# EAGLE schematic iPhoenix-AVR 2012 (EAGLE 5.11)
COMPANY: AL-AWAIL; DATE-YEAR: 11

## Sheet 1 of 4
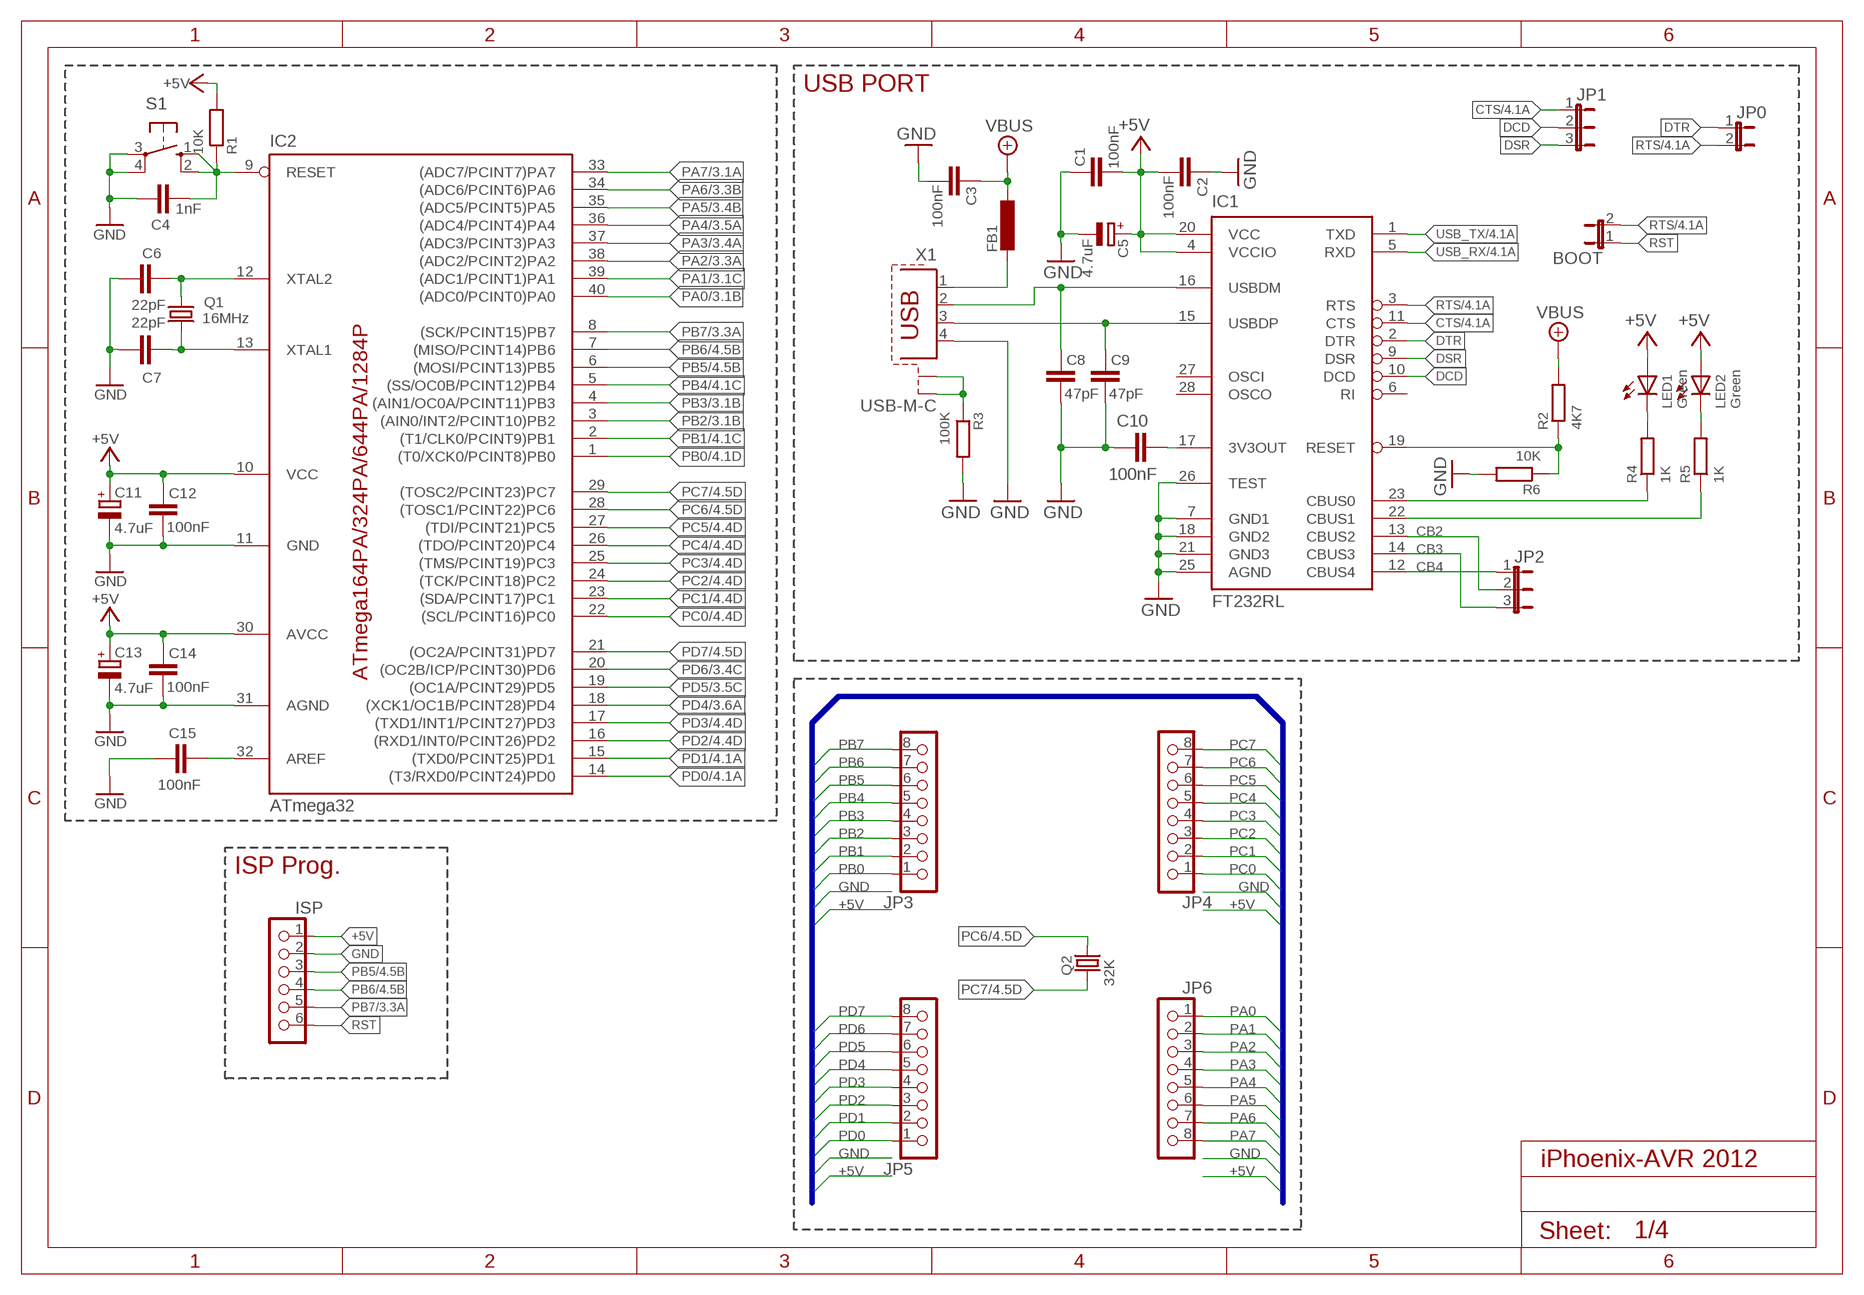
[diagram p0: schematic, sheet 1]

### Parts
BOOT  JP1E  [JP1]
C1  100nF  CAPC025-025X050  [C025-025X050]
C2  100nF  CAPC025-025X050  [C025-025X050]
C3  100nF  CAPC025-025X050  [C025-025X050]
C4  1nF  CAPC025-025X050  [C025-025X050]
C5  4.7uF  ELCE2,5-5  [E2,5-5]
C6  22pF  CAPC025-025X050  [C025-025X050]
C7  22pF  CAPC025-025X050  [C025-025X050]
C8  47pF  CAPC025-025X050  [C025-025X050]
C9  47pF  CAPC025-025X050  [C025-025X050]
C10  100nF  CAPC025-025X050  [C025-025X050]
C11  4.7uF  ELCE2,5-5  [E2,5-5]
C12  100nF  CAPC025-025X050  [C025-025X050]
C13  4.7uF  ELCE2,5-5  [E2,5-5]
C14  100nF  CAPC025-025X050  [C025-025X050]
C15  100nF  CAPC025-025X050  [C025-025X050]
FB1  FB1206  [R1206]
IC1  FT232RL  [SSOP28]
IC2  ATmega32  ATMEGA324P  [DIL40]
ISP  PINHD-1X6  [1X06]
JP0  JP1E  [JP1]
JP1  JP2EA  [JP2]
JP2  JP2EA  [JP2]
JP3  PINHD-1X8  [1X08]
JP4  PINHD-1X8  [1X08]
JP5  PINHD-1X8  [1X08]
JP6  PINHD-1X8  [1X08]
LED1  Green  LED3  [LED3MM]
LED2  Green  LED3  [LED3MM]
Q1  16MHz  CRYSTALHC  [HC49]
Q2  32K  CRYSTALTC  [TC26]
R1  10K  RESISTOR0207/8  [0207/8]
R2  4K7  RESISTOR0207/8  [0207/8]
R3  100K  RESISTOR0207/8  [0207/8]
R4  1K  RESISTOR0207/8  [0207/8]
R5  1K  RESISTOR0207/8  [0207/8]
R6  10K  RESISTOR0207/8  [0207/8]
S1  TAC_SW_M  [B3F-10XX]
X1  USB-M-C  [PN61729-S]

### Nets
+5V: C1.2 C2.2 C5.+ C11.+ C12.1 C13.+ C14.1 IC1.4(VCCIO) IC1.20(VCC) IC2.10(VCC) IC2.30(AVCC) ISP.1 LED1.A LED2.A R1.2 ; also sheet 2,3,4
+5V/1: C3.1 FB1.1 R2.2 ; supply symbol labelled VBUS ; also sheet 2
CB2: IC1.13(CBUS2) JP2.2
CB3: IC1.14(CBUS3) JP2.3
CB4: IC1.12(CBUS4) JP2.1
CTS: IC1.11(CTS) JP1.1 ; also sheet 4
DCD: IC1.10(DCD) JP1.2
DSR: IC1.9(DSR) JP1.3
DTR: IC1.2(DTR) JP0.1
GND: C1.1 C2.1 C3.2 C4.1 C5.- C6.2 C7.2 C8.2 C9.2 C10.2 C11.- C12.2 C13.- C14.2 C15.2 IC1.7(GND1) IC1.18(GND2) IC1.21(GND3) IC1.25(AGND) IC1.26(TEST) IC2.11(GND) IC2.31(AGND) ISP.2 R3.2 R6.2 S1.3(P) S1.4(P1) X1.4 ; also sheet 2,3,4
N$2: C6.1 IC2.12(XTAL2) Q1.1
N$8: C15.1 IC2.32(AREF)
N$13: R3.1 X1.S1 X1.S2
N$161: IC1.23(CBUS0) R4.1
N$197: C8.1 IC1.16(USBDM) X1.2
N$199: C9.1 IC1.15(USBDP) X1.3
N$200: C10.1 IC1.17(3V3OUT)
N$201: IC1.19(RESET) R2.1 R6.1
N$202: IC1.22(CBUS1) R5.1
N$203: LED1.K(C) R4.2
N$235: LED2.K(C) R5.2
PA0: IC2.40((ADC0/PCINT0)PA0) JP6.1 ; also sheet 3
PA1: IC2.39((ADC1/PCINT1)PA1) JP6.2 ; also sheet 3
PA2: IC2.38((ADC2/PCINT2)PA2) JP6.3 ; also sheet 3
PA3: IC2.37((ADC3/PCINT3)PA3) JP6.4 ; also sheet 3
PA4: IC2.36((ADC4/PCINT4)PA4) JP6.5 ; also sheet 3
PA5: IC2.35((ADC5/PCINT5)PA5) JP6.6 ; also sheet 3
PA6: IC2.34((ADC6/PCINT6)PA6) JP6.7 ; also sheet 3
PA7: IC2.33((ADC7/PCINT7)PA7) JP6.8 ; also sheet 3
PB0: IC2.1((T0/XCK0/PCINT8)PB0) JP3.1 ; also sheet 2,4
PB1: IC2.2((T1/CLK0/PCINT9)PB1) JP3.2 ; also sheet 2,4
PB2: IC2.3((AIN0/INT2/PCINT10)PB2) JP3.3 ; also sheet 2,3,4
PB3: IC2.4((AIN1/OC0A/PCINT11)PB3) JP3.4 ; also sheet 2,3,4
PB4: IC2.5((SS/OC0B/PCINT12)PB4) JP3.5 ; also sheet 2,4
PB5: IC2.6((MOSI/PCINT13)PB5) ISP.3 JP3.6 ; also sheet 2,4
PB6: IC2.7((MISO/PCINT14)PB6) ISP.4 JP3.7 ; also sheet 2,4
PB7: IC2.8((SCK/PCINT15)PB7) ISP.5 JP3.8 ; also sheet 2,3,4
PC0: IC2.22((SCL/PCINT16)PC0) JP4.1 ; also sheet 2,4
PC1: IC2.23((SDA/PCINT17)PC1) JP4.2 ; also sheet 2,4
PC2: IC2.24((TCK/PCINT18)PC2) JP4.3 ; also sheet 2,4
PC3: IC2.25((TMS/PCINT19)PC3) JP4.4 ; also sheet 2,4
PC4: IC2.26((TDO/PCINT20)PC4) JP4.5 ; also sheet 2,4
PC5: IC2.27((TDI/PCINT21)PC5) JP4.6 ; also sheet 2,4
PC6: IC2.28((TOSC1/PCINT22)PC6) JP4.7 Q2.2 ; also sheet 2,4
PC7: IC2.29((TOSC2/PCINT23)PC7) JP4.8 Q2.1 ; also sheet 2,4
PD0: IC2.14((T3/RXD0/PCINT24)PD0) JP5.1 ; also sheet 4
PD1: IC2.15((TXD0/PCINT25)PD1) JP5.2 ; also sheet 4
PD2: IC2.16((RXD1/INT0/PCINT26)PD2) JP5.3 ; also sheet 2,4
PD3: IC2.17((TXD1/INT1/PCINT27)PD3) JP5.4 ; also sheet 2,4
PD4: IC2.18((XCK1/OC1B/PCINT28)PD4) JP5.5 ; also sheet 3,4
PD5: IC2.19((OC1A/PCINT29)PD5) JP5.6 ; also sheet 3,4
PD6: IC2.20((OC2B/ICP/PCINT30)PD6) JP5.7 ; also sheet 3,4
PD7: IC2.21((OC2A/PCINT31)PD7) JP5.8 ; also sheet 4
RST: BOOT.1 C4.2 IC2.9(RESET) ISP.6 R1.1 S1.1(S) S1.2(S1)
RTS: BOOT.2 IC1.3(RTS) JP0.2 ; also sheet 4
USB_RX: IC1.5(RXD) ; also sheet 4
USB_TX: IC1.1(TXD) ; also sheet 4
VUSB: FB1.2 X1.1
XT2: C7.1 IC2.13(XTAL1) Q1.2
Unconnected: IC1.6(RI) IC1.27(OSCI) IC1.28(OSCO)

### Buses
PA[0..7],PB[0..7],PC[0..7],PD[0..7],PE[0..7],PF[0..7],+5V,GND

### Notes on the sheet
- USB PORT
- ISP Prog.

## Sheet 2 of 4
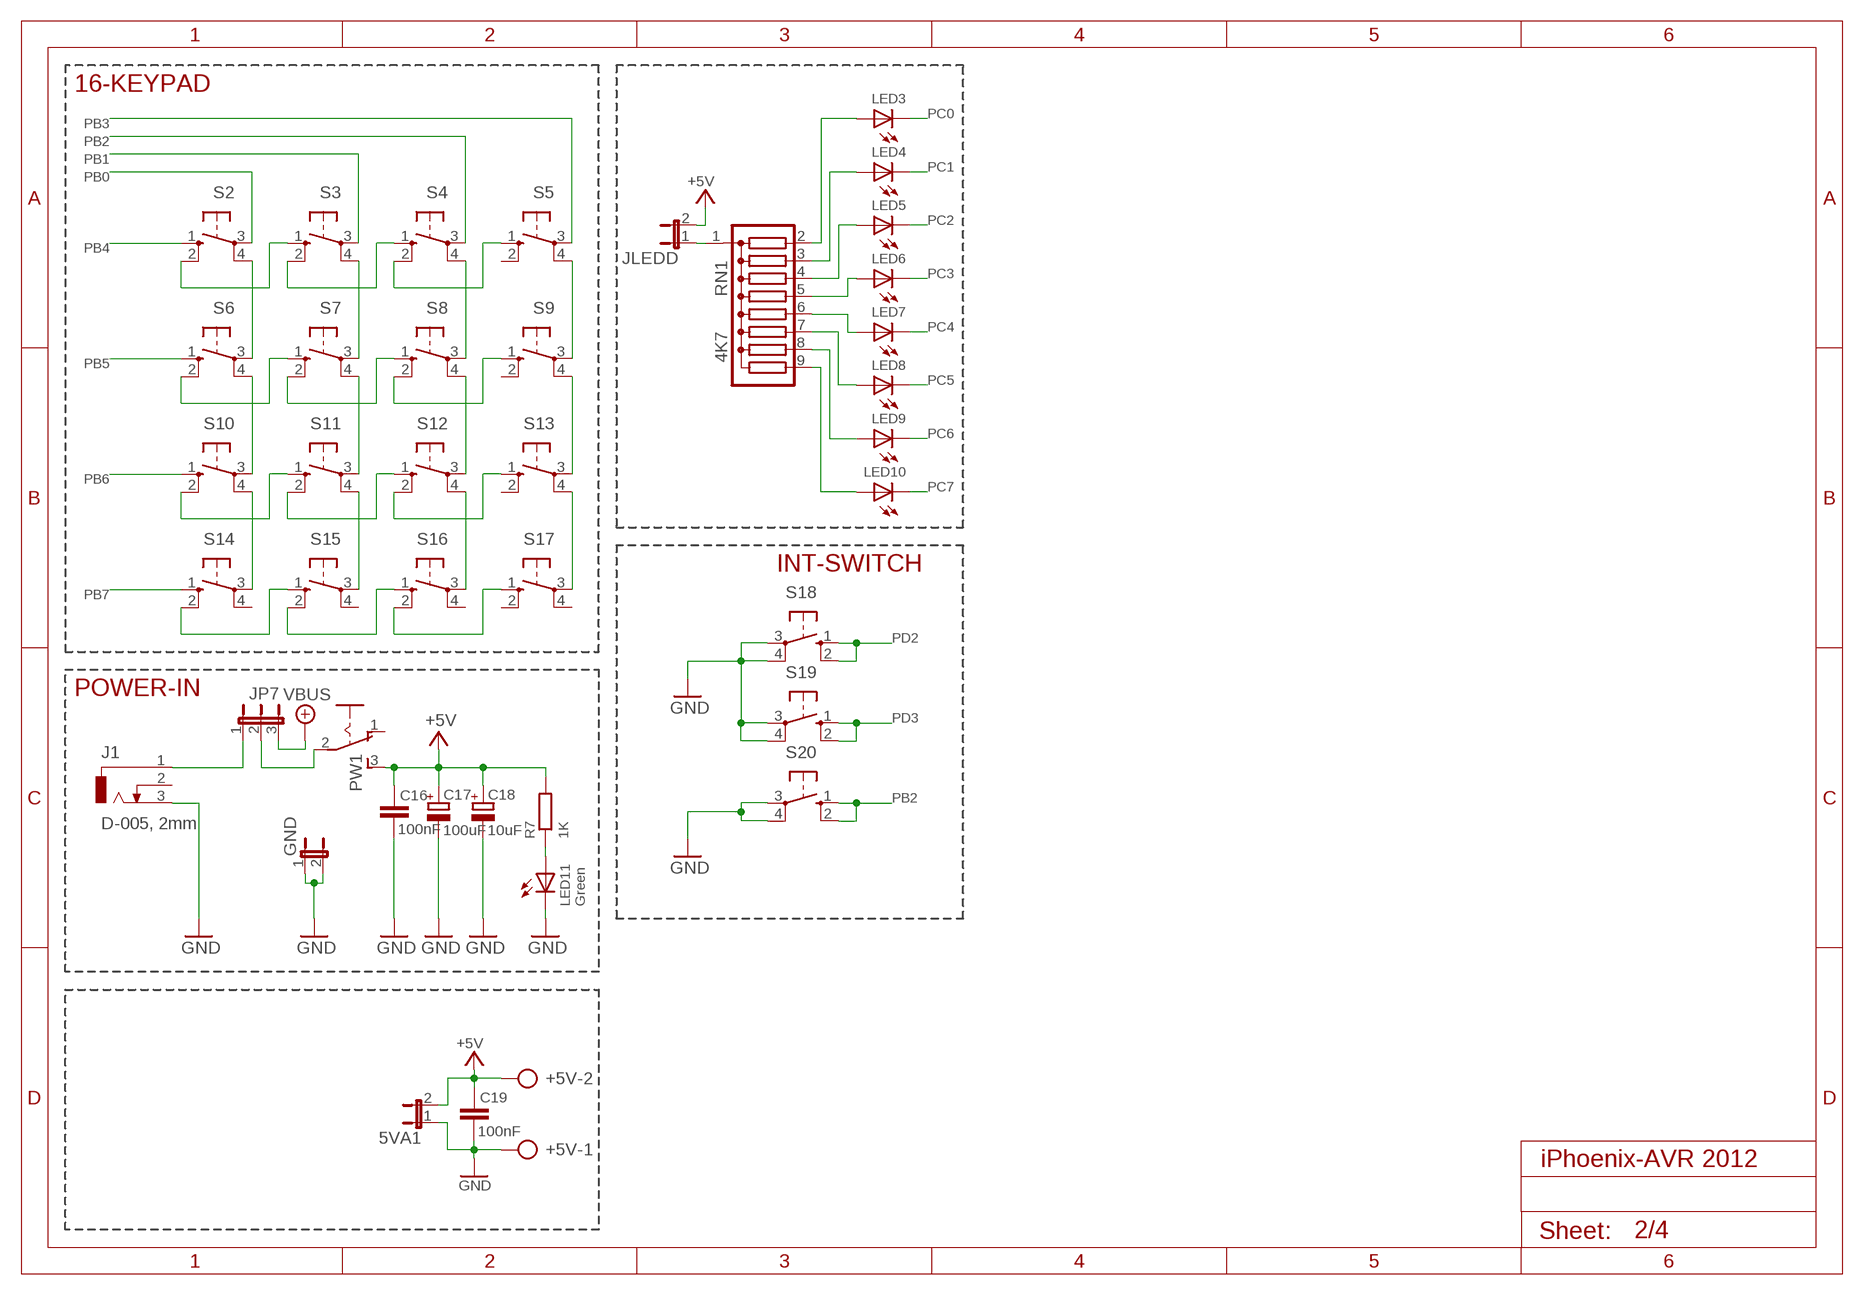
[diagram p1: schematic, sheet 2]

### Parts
5VA1  JP1E  [JP1]
+5V  AK500/2  [AK500/2]
C16  100nF  CAPC025-025X050  [C025-025X050]
C17  100uF  ELCE2,5-5  [E2,5-5]
C18  10uF  ELCE2,5-5  [E2,5-5]
C19  100nF  CAPC025-025X050  [C025-025X050]
GND  JP1E  [JP1]
J1  D-005, 2mm  DCJ0202  [DCJ0202]
JLEDD  JP1E  [JP1]
JP7  JP2EA  [JP2]
LED3  LED3  [LED3MM]
LED4  LED3  [LED3MM]
LED5  LED3  [LED3MM]
LED6  LED3  [LED3MM]
LED7  LED3  [LED3MM]
LED8  LED3  [LED3MM]
LED9  LED3  [LED3MM]
LED10  LED3  [LED3MM]
LED11  Green  LED3  [LED3MM]
PW1  SW-ON-OFF3  [230SB]
R7  1K  RESISTOR0207/8  [0207/8]
RN1  4K7  G08R  [SIL9]
S2  TAC_SW_M  [B3F-10XX]
S3  TAC_SW_M  [B3F-10XX]
S4  TAC_SW_M  [B3F-10XX]
S5  TAC_SW_M  [B3F-10XX]
S6  TAC_SW_M  [B3F-10XX]
S7  TAC_SW_M  [B3F-10XX]
S8  TAC_SW_M  [B3F-10XX]
S9  TAC_SW_M  [B3F-10XX]
S10  TAC_SW_M  [B3F-10XX]
S11  TAC_SW_M  [B3F-10XX]
S12  TAC_SW_M  [B3F-10XX]
S13  TAC_SW_M  [B3F-10XX]
S14  TAC_SW_M  [B3F-10XX]
S15  TAC_SW_M  [B3F-10XX]
S16  TAC_SW_M  [B3F-10XX]
S17  TAC_SW_M  [B3F-10XX]
S18  TAC_SW_M  [B3F-10XX]
S19  TAC_SW_M  [B3F-10XX]
S20  TAC_SW_M  [B3F-10XX]

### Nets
+5V: 5VA1.2 +5V.2 C16.1 C17.+ C18.+ C19.1 JLEDD.2 PW1.3(S) R7.2 ; also sheet 1,3,4
+5V/1: JP7.3 ; supply symbol labelled VBUS ; also sheet 1
GND: 5VA1.1 +5V.1 C16.2 C17.- C18.- C19.2 GND.1 GND.2 J1.3 LED11.K(C) S18.3(P) S18.4(P1) S19.3(P) S19.4(P1) S20.3(P) S20.4(P1) ; also sheet 1,3,4
N$14: LED11.A R7.1
N$15: J1.1 JP7.1
N$16: JP7.2 PW1.2(P)
N$36: S2.2(S1) S3.1(S)
N$37: S3.2(S1) S4.1(S)
N$38: S4.2(S1) S5.1(S)
N$39: S10.2(S1) S11.1(S)
N$40: S11.2(S1) S12.1(S)
N$41: S12.2(S1) S13.1(S)
N$60: S6.2(S1) S7.1(S)
N$61: S7.2(S1) S8.1(S)
N$62: S8.2(S1) S9.1(S)
N$65: S14.2(S1) S15.1(S)
N$66: S15.2(S1) S16.1(S)
N$67: S2.4(P1) S6.3(P)
N$68: S3.4(P1) S7.3(P)
N$69: S4.4(P1) S8.3(P)
N$70: S5.4(P1) S9.3(P)
N$71: S16.2(S1) S17.1(S)
N$73: S10.4(P1) S14.3(P)
N$74: S11.4(P1) S15.3(P)
N$75: S12.4(P1) S16.3(P)
N$76: S13.4(P1) S17.3(P)
N$77: S6.4(P1) S10.3(P)
N$78: S7.4(P1) S11.3(P)
N$79: S8.4(P1) S12.3(P)
N$80: S9.4(P1) S13.3(P)
N$288: JLEDD.1 RN1.1
N$293: LED3.A RN1.2
N$294: LED4.A RN1.3
N$295: LED5.A RN1.4
N$296: LED6.A RN1.5
N$297: LED10.A RN1.9
N$298: LED9.A RN1.8
N$299: LED8.A RN1.7
N$303: LED7.A RN1.6
PB0: S2.3(P) ; also sheet 1,4
PB1: S3.3(P) ; also sheet 1,4
PB2: S4.3(P) S20.1(S) S20.2(S1) ; also sheet 1,3,4
PB3: S5.3(P) ; also sheet 1,3,4
PB4: S2.1(S) ; also sheet 1,4
PB5: S6.1(S) ; also sheet 1,4
PB6: S10.1(S) ; also sheet 1,4
PB7: S14.1(S) ; also sheet 1,3,4
PC0: LED3.K(C) ; also sheet 1,4
PC1: LED4.K(C) ; also sheet 1,4
PC2: LED5.K(C) ; also sheet 1,4
PC3: LED6.K(C) ; also sheet 1,4
PC4: LED7.K(C) ; also sheet 1,4
PC5: LED8.K(C) ; also sheet 1,4
PC6: LED9.K(C) ; also sheet 1,4
PC7: LED10.K(C) ; also sheet 1,4
PD2: S18.1(S) S18.2(S1) ; also sheet 1,4
PD3: S19.1(S) S19.2(S1) ; also sheet 1,4
Unconnected: J1.2 PW1.1(O) S5.2(S1) S9.2(S1) S13.2(S1) S14.4(P1) S15.4(P1) S16.4(P1) S17.2(S1) S17.4(P1)

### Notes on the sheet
- 16-KEYPAD
- INT-SWITCH
- POWER-IN

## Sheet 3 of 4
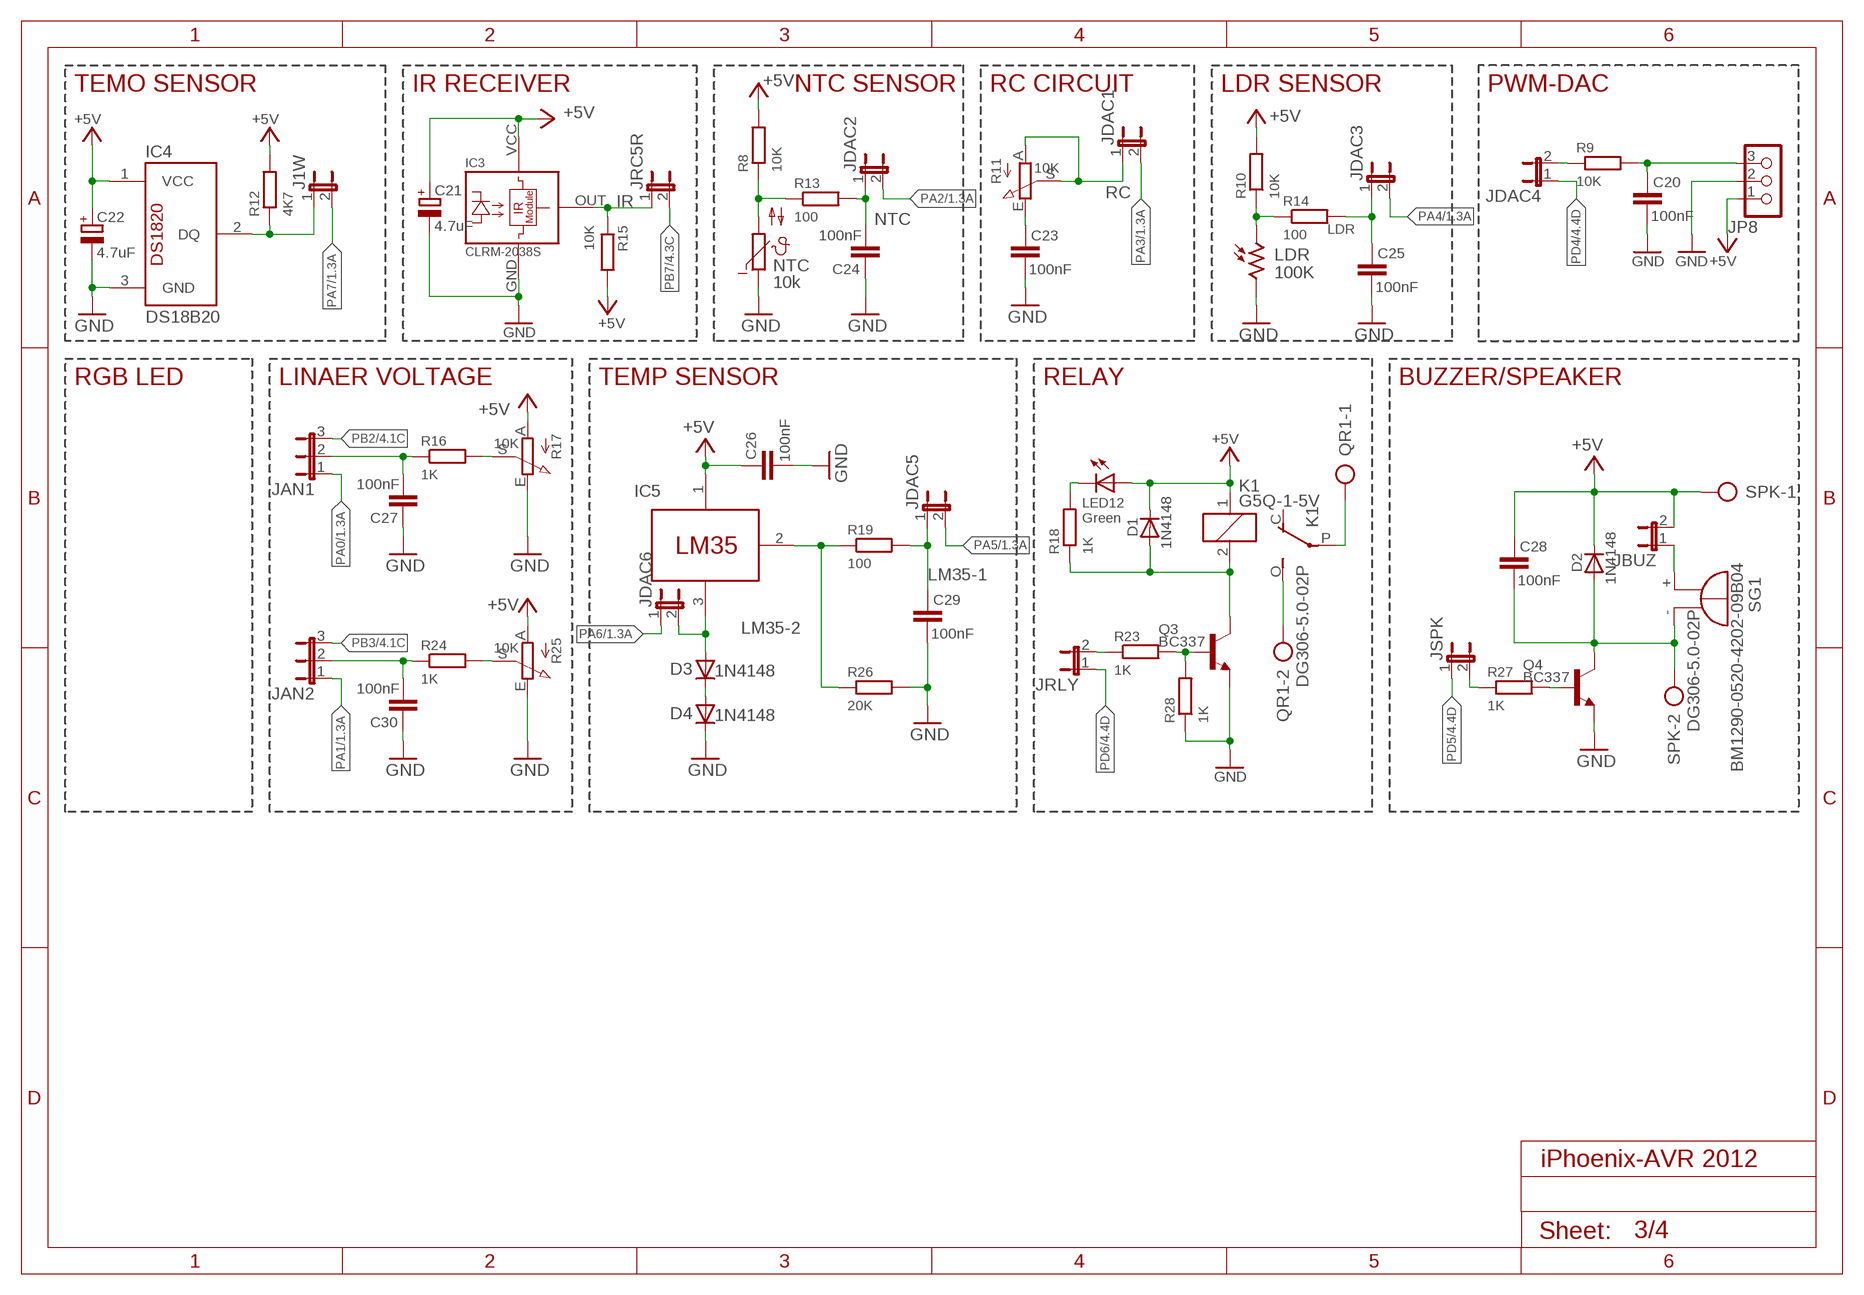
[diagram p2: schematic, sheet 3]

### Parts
C20  100nF  CAPC025-025X050  [C025-025X050]
C21  4.7uF  ELCE2,5-5  [E2,5-5]
C22  4.7uF  ELCE2,5-5  [E2,5-5]
C23  100nF  CAPC025-025X050  [C025-025X050]
C24  100nF  CAPC025-025X050  [C025-025X050]
C25  100nF  CAPC025-025X050  [C025-025X050]
C26  100nF  CAPC025-025X050  [C025-025X050]
C27  100nF  CAPC025-025X050  [C025-025X050]
C28  100nF  CAPC025-025X050  [C025-025X050]
C29  100nF  CAPC025-025X050  [C025-025X050]
C30  100nF  CAPC025-025X050  [C025-025X050]
D1  1N4148  1N4148-7  [DO35-7]
D2  1N4148  1N4148-7  [DO35-7]
D3  1N4148  1N4148-7  [DO35-7]
D4  1N4148  1N4148-7  [DO35-7]
IC3  CLRM-2038S  IR-RECEIVERIR  [IR-RECEIVER]
IC4  DS18B20  DS1820  [TO92L]
IC5  LM35DZ  LM35  [LM35]
J1W  JP1E  [JP1]
JAN1  JP2EA  [JP2]
JAN2  JP2EA  [JP2]
JBUZ  JP1E  [JP1]
JDAC1  JP1E  [JP1]
JDAC2  JP1E  [JP1]
JDAC3  JP1E  [JP1]
JDAC4  JP1E  [JP1]
JDAC5  JP1E  [JP1]
JDAC6  JP1E  [JP1]
JP8  PINHD-1X3  [1X03]
JRC5R  JP1E  [JP1]
JRLY  JP1E  [JP1]
JSPK  JP1E  [JP1]
K1  G5Q-1-5V  G5Q-1R  [G5Q]
LDR  100K  V1060_32  [TO-5_V10]
LED12  Green  LED3  [LED3MM]
NTC  10k  NTCW  [N640W]
Q3  BC337  [TO92]
Q4  BC337  [TO92]
QR1  DG306-5.0-02P  AK500/2  [AK500/2]
R8  10K  RESISTOR0207/8  [0207/8]
R9  10K  RESISTOR0207/8  [0207/8]
R10  10K  RESISTOR0207/8  [0207/8]
R11  10K  POT  [POT]
R12  4K7  RESISTOR0207/8  [0207/8]
R13  100  RESISTOR0207/8  [0207/8]
R14  100  RESISTOR0207/8  [0207/8]
R15  10K  RESISTOR0207/8  [0207/8]
R16  1K  RESISTOR0207/8  [0207/8]
R17  10K  POT  [POT]
R18  1K  RESISTOR0207/8  [0207/8]
R19  100  RESISTOR0207/8  [0207/8]
R23  1K  RESISTOR0207/8  [0207/8]
R24  1K  RESISTOR0207/8  [0207/8]
R25  10K  POT  [POT]
R26  20K  RESISTOR0207/8  [0207/8]
R27  1K  RESISTOR0207/8  [0207/8]
R28  1K  RESISTOR0207/8  [0207/8]
SG1  BM1290-0520-4202-09B04  BUZZERB  [F/TAT]
SPK  DG306-5.0-02P  AK500/2  [AK500/2]

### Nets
+5V: C21.+ C22.+ C26.1 C28.1 D1.C D2.C IC3.VCC IC4.1(VCC) IC5.1(VCC) JBUZ.2 JP8.1 K1.1 LED12.A R8.2 R10.2 R12.2 R15.2 R17.A R25.A SPK.1 ; also sheet 1,2,4
GND: C20.2 C21.- C22.- C23.2 C24.1 C25.2 C26.2 C27.1 C29.2 C30.1 D4.C IC3.GND IC4.3(GND) JP8.2 LDR.2 NTC.1 Q3.1(E) Q4.1(E) R17.E R25.E R26.2 R28.1 ; also sheet 1,2,4
GROUP-A1: JRLY.2 R23.1
IR: IC3.OUT JRC5R.1 R15.1
LDR: C25.1 JDAC3.1 R14.2
LM35-1: C29.1 JDAC5.1 R19.2
LM35-2: D3.A IC5.3(GND) JDAC6.2
N$3: JBUZ.1 SG1.+
N$4: C20.1 JP8.3 R9.2
N$5: JDAC4.2 R9.1
N$130: IC5.2(VO) R19.1 R26.1
N$131: D3.C D4.A
N$132: R16.2 R17.S
N$137: IC4.2(DQ) J1W.1 R12.1
N$146: NTC.2 R8.1 R13.1
N$152: R24.2 R25.S
N$153: C27.2 JAN1.2 R16.1
N$154: C30.2 JAN2.2 R24.1
N$155: LDR.1 R10.1 R14.1
N$163: C28.2 D2.A Q4.3(C) SG1.- SPK.2
N$164: Q4.2(B) R27.2
N$165: JSPK.2 R27.1
N$236: C23.1 R11.E
N$238: Q3.2(B) R23.2 R28.2
N$239: LED12.K(C) R18.2
N$240: D1.A K1.2 Q3.3(C) R18.1
N$241: K1.O(2:S) QR1.2
N$254: K1.P(2:P) QR1.1
NTC: C24.2 JDAC2.1 R13.2
PA0: JAN1.1 ; also sheet 1
PA1: JAN2.1 ; also sheet 1
PA2: JDAC2.2 ; also sheet 1
PA3: JDAC1.2 ; also sheet 1
PA4: JDAC3.2 ; also sheet 1
PA5: JDAC5.2 ; also sheet 1
PA6: JDAC6.1 ; also sheet 1
PA7: J1W.2 ; also sheet 1
PB2: JAN1.3 ; also sheet 1,2,4
PB3: JAN2.3 ; also sheet 1,2,4
PB7: JRC5R.2 ; also sheet 1,2,4
PD4: JDAC4.1 ; also sheet 1,4
PD5: JSPK.1 ; also sheet 1,4
PD6: JRLY.1 ; also sheet 1,4
RC: JDAC1.1 R11.A R11.S
Unconnected: K1.C(2:O)

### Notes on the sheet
- TEMO SENSOR | IR RECEIVER | NTC SENSOR | RC CIRCUIT | LDR SENSOR | PWM-DAC
- RGB LED | LINAER VOLTAGE | TEMP SENSOR | RELAY | BUZZER/SPEAKER

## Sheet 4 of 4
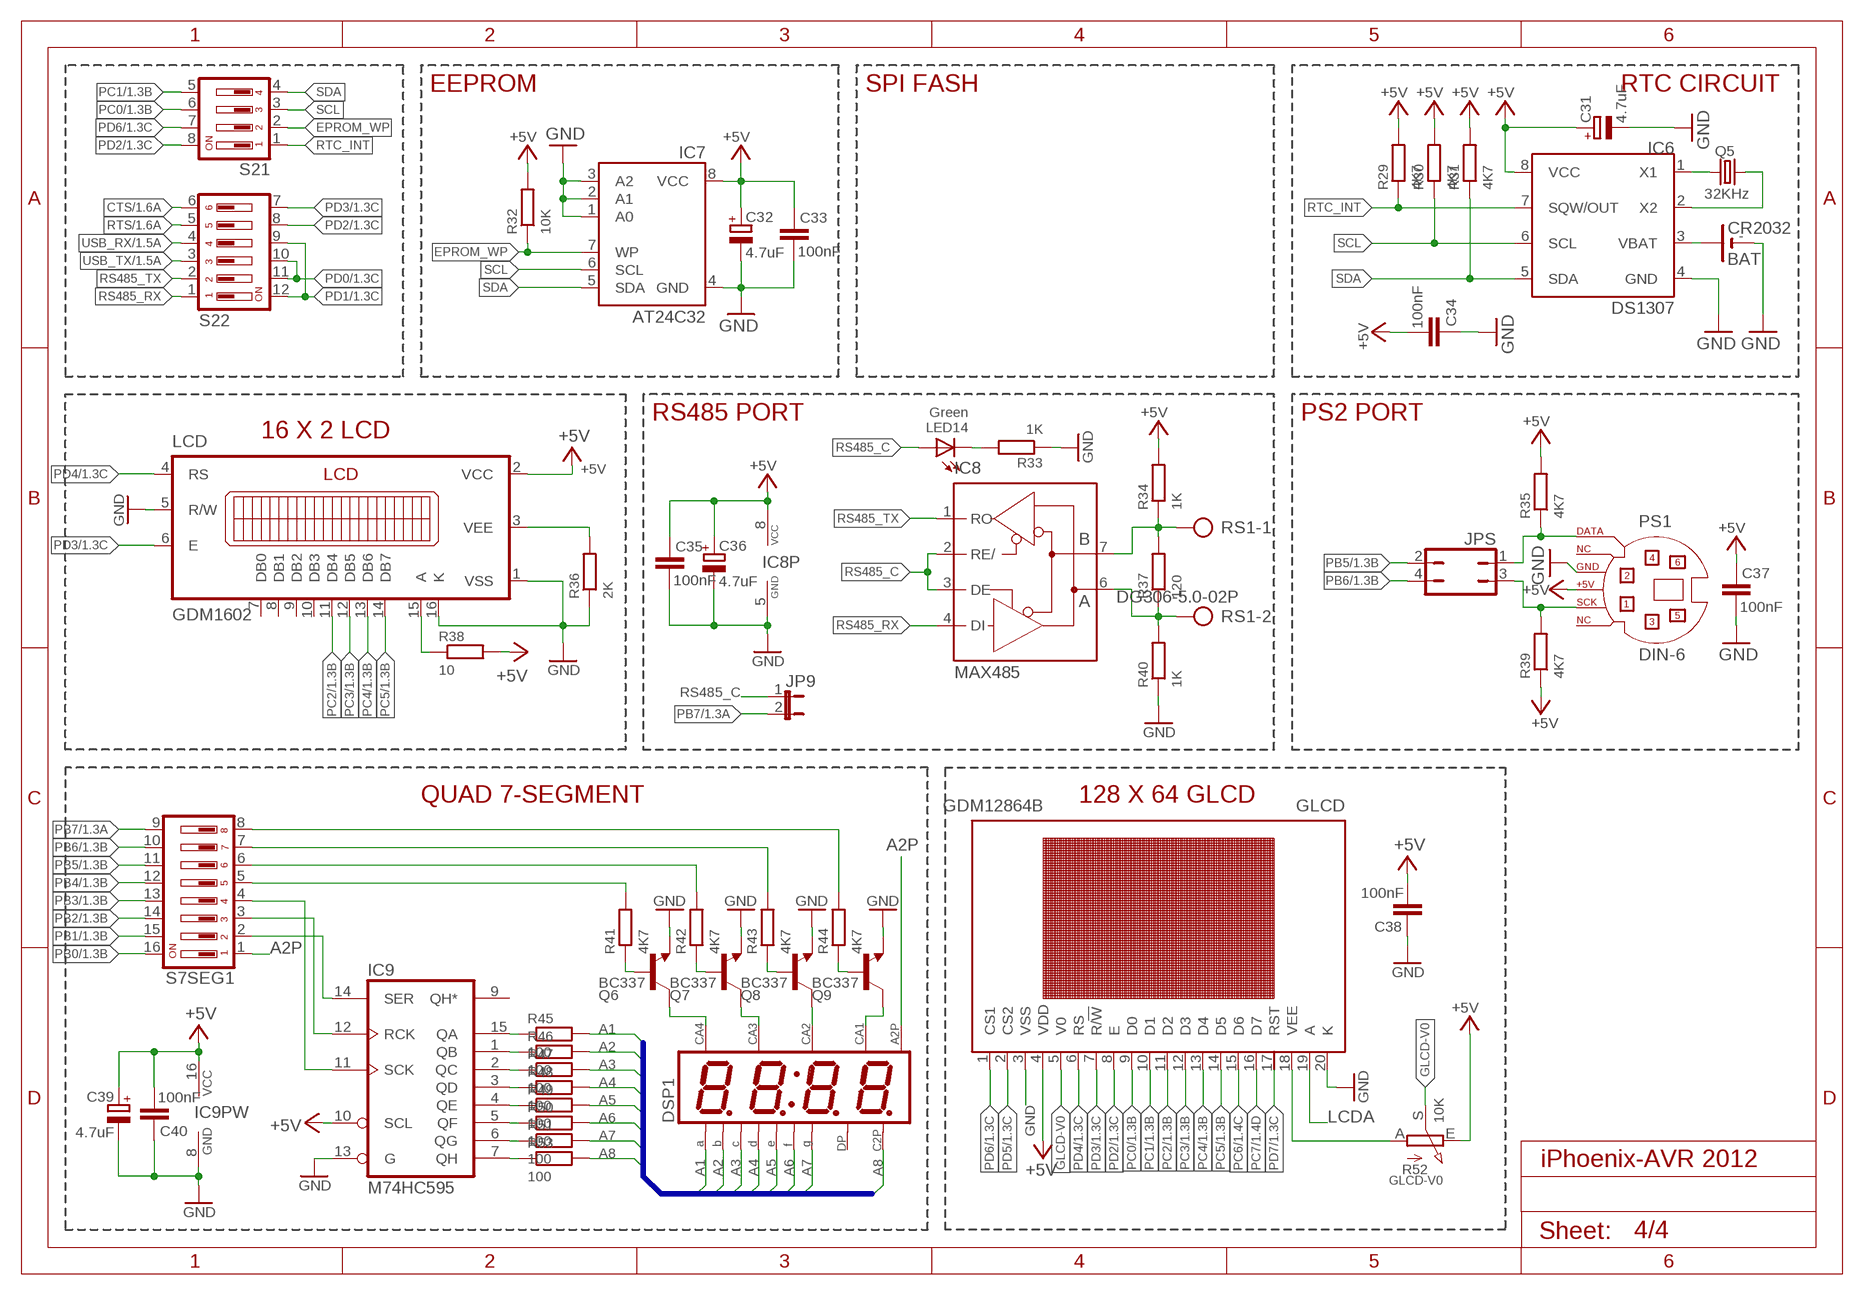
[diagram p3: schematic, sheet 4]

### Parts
BAT  CR2032  BATTB  [BATT]
C31  4.7uF  ELCE2,5-5  [E2,5-5]
C32  4.7uF  ELCE2,5-5  [E2,5-5]
C33  100nF  CAPC025-025X050  [C025-025X050]
C34  100nF  CAPC025-025X050  [C025-025X050]
C35  100nF  CAPC025-025X050  [C025-025X050]
C36  4.7uF  ELCE2,5-5  [E2,5-5]
C37  100nF  CAPC025-025X050  [C025-025X050]
C38  100nF  CAPC025-025X050  [C025-025X050]
C39  4.7uF  ELCE2,5-5  [E2,5-5]
C40  100nF  CAPC025-025X050  [C025-025X050]
DSP1  F512SRWBT14  [F512SRWBT14]
GLCD  GDM12864B  LCD128X64B  [GDM12864B]
IC6  DS1307  [DIL8O]
IC7  AT24C32  AT24CR  [DIL8R]
IC8  MAX485  MAX485P  [DIL8R]
IC9  M74HC595  74HC595R  [DIL16R]
JP9  JP1E  [JP1]
JPS  JP2Q  [JP2Q]
LCD  GDM1602  LCD16X2  [DMC-162C]
LED14  Green  LED3  [LED3MM]
PS1  DIN-6  PS2-CON  [PS2-CON]
Q5  32KHz  CRYSTALTC  [TC26]
Q6  BC337  [TO92]
Q7  BC337  [TO92]
Q8  BC337  [TO92]
Q9  BC337  [TO92]
R29  4K7  RESISTOR0207/8  [0207/8]
R30  4K7  RESISTOR0207/8  [0207/8]
R31  4K7  RESISTOR0207/8  [0207/8]
R32  10K  RESISTOR0207/8  [0207/8]
R33  1K  RESISTOR0207/8  [0207/8]
R34  1K  RESISTOR0207/8  [0207/8]
R35  4K7  RESISTOR0207/8  [0207/8]
R36  2K  RESISTOR0207/8  [0207/8]
R37  120  RESISTOR0207/8  [0207/8]
R38  10  RESISTOR0207/8  [0207/8]
R39  4K7  RESISTOR0207/8  [0207/8]
R40  1K  RESISTOR0207/8  [0207/8]
R41  4K7  RESISTOR0207/8  [0207/8]
R42  4K7  RESISTOR0207/8  [0207/8]
R43  4K7  RESISTOR0207/8  [0207/8]
R44  4K7  RESISTOR0207/8  [0207/8]
R45  100  RESISTOR0207/8  [0207/8]
R46  100  RESISTOR0207/8  [0207/8]
R47  100  RESISTOR0207/8  [0207/8]
R48  100  RESISTOR0207/8  [0207/8]
R49  100  RESISTOR0207/8  [0207/8]
R50  100  RESISTOR0207/8  [0207/8]
R51  100  RESISTOR0207/8  [0207/8]
R52  10K  POT  [POT]
R53  100  RESISTOR0207/8  [0207/8]
RS1  DG306-5.0-02P  AK500/2  [AK500/2]
S7SEG1  DIP08YL  [DIP08YL]
S21  DIP04YL  [DIP04YL]
S22  DIP06YL  [DIP06YL]

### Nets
+5V: C31.+ C32.+ C33.1 C34.2 C35.1 C36.+ C37.1 C38.2 C39.+ C40.2 GLCD.4(VDD) IC6.8(VCC) IC7.8(VCC) IC8.8(VCC) IC9.10(SCL) IC9.16(VCC) LCD.2(VCC) PS1.4 R29.2 R30.2 R31.2 R32.2 R34.2 R35.2 R38.2 R39.1 R52.E ; also sheet 1,2,3
A1: DSP1.13(A) R45.2
A2: DSP1.9(B) R46.2
A2P: DSP1.7(A2P) S7SEG1.1
A3: DSP1.4(C) R47.2
A4: DSP1.2(D) R48.2
A5: DSP1.1(E) R49.2
A6: DSP1.12(F) R50.2
A7: DSP1.5(G) R51.2
A8: DSP1.8(C2P) R53.2
AR11: IC8.7(B) R34.1 R37.2 RS1.1
CTS: S22.6 ; also sheet 1
EPROM_WP: IC7.7(WP) R32.1 S21.2
GLCD-V0: GLCD.5(V0) R52.S
GLCD-VEE: GLCD.18(VEE) R52.A
GND: BAT.- C31.- C32.- C33.2 C34.1 C35.2 C36.- C37.2 C38.1 C39.- C40.1 GLCD.3(VSS) GLCD.20(K) IC6.4(GND) IC7.1(A0) IC7.2(A1) IC7.3(A2) IC7.4(GND) IC8.5(GND) IC9.8(GND) IC9.13(G) LCD.1(VSS) LCD.5(R/W) LCD.16(K) PS1.3 Q6.1(E) Q7.1(E) Q8.1(E) Q9.1(E) R33.1 R36.1 R40.1 ; also sheet 1,2,3
LCDA: GLCD.19(A) LCD.15(A) R38.1
N$1: IC6.1(X1) Q5.1
N$7: IC6.2(X2) Q5.2
N$9: BAT.+ IC6.3(VBAT)
N$63: LCD.3(VEE) R36.2
N$81: IC9.15(QA) R45.1
N$82: IC9.1(QB) R46.1
N$83: IC9.2(QC) R47.1
N$84: IC9.3(QD) R48.1
N$95: IC9.4(QE) R49.1
N$96: IC9.5(QF) R50.1
N$100: IC9.6(QG) R51.1
N$103: LED14.K(C) R33.2
N$113: IC9.7(QH) R53.1
N$114: DSP1.14(CA1) Q9.3(C)
N$115: DSP1.11(CA2) Q8.3(C)
N$116: DSP1.10(CA3) Q7.3(C)
N$117: DSP1.6(CA4) Q6.3(C)
N$118: IC9.14(SER) S7SEG1.2
N$119: IC9.12(RCK) S7SEG1.3
N$120: IC9.11(SCK) S7SEG1.4
N$122: Q9.2(B) R44.1
N$123: Q8.2(B) R43.1
N$124: Q7.2(B) R42.1
N$125: Q6.2(B) R41.1
N$126: R41.2 S7SEG1.5
N$127: R42.2 S7SEG1.6
N$128: R43.2 S7SEG1.7
N$129: R44.2 S7SEG1.8
N$228: IC8.6(A) R37.1 R40.2 RS1.2
P25: JPS.3 PS1.5 R39.2
P43: JPS.1 PS1.1 R35.1
PB0: S7SEG1.16 ; also sheet 1,2
PB1: S7SEG1.15 ; also sheet 1,2
PB2: S7SEG1.14 ; also sheet 1,2,3
PB3: S7SEG1.13 ; also sheet 1,2,3
PB4: S7SEG1.12 ; also sheet 1,2
PB5: JPS.2 S7SEG1.11 ; also sheet 1,2
PB6: JPS.4 S7SEG1.10 ; also sheet 1,2
PB7: JP9.2 S7SEG1.9 ; also sheet 1,2,3
PC0: GLCD.9(D0) S21.6 ; also sheet 1,2
PC1: GLCD.10(D1) S21.5 ; also sheet 1,2
PC2: GLCD.11(D2) LCD.11(DB4) ; also sheet 1,2
PC3: GLCD.12(D3) LCD.12(DB5) ; also sheet 1,2
PC4: GLCD.13(D4) LCD.13(DB6) ; also sheet 1,2
PC5: GLCD.14(D5) LCD.14(DB7) ; also sheet 1,2
PC6: GLCD.15(D6) ; also sheet 1,2
PC7: GLCD.16(D7) ; also sheet 1,2
PD0: S22.10 S22.11 ; also sheet 1
PD1: S22.9 S22.12 ; also sheet 1
PD2: GLCD.8(E) S21.8 S22.8 ; also sheet 1,2
PD3: GLCD.7(R/!W) LCD.6(E) S22.7 ; also sheet 1,2
PD4: GLCD.6(RS) LCD.4(RS) ; also sheet 1,3
PD5: GLCD.2(CS2) ; also sheet 1,3
PD6: GLCD.1(CS1) S21.7 ; also sheet 1,3
PD7: GLCD.17(RST) ; also sheet 1
RS485_C: IC8.2(RE/) IC8.3(DE) JP9.1 LED14.A
RS485_RX: IC8.4(DI) S22.1
RS485_TX: IC8.1(RO) S22.2
RTC_INT: IC6.7(SQW/OUT) R29.1 S21.1
RTS: S22.5 ; also sheet 1
SCL: IC6.6(SCL) IC7.6(SCL) R30.1 S21.3
SDA: IC6.5(SDA) IC7.5(SDA) R31.1 S21.4
USB_RX: S22.4 ; also sheet 1
USB_TX: S22.3 ; also sheet 1
Unconnected: DSP1.3(DP) IC9.9(QH*) LCD.7(DB0) LCD.8(DB1) LCD.9(DB2) LCD.10(DB3) PS1.2 PS1.6

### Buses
A[1..8]

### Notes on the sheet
- EEPROM | SPI FASH | RTC CIRCUIT
- RS485 PORT | PS2 PORT
- 16 X 2 LCD
- QUAD 7-SEGMENT | 128 X 64 GLCD

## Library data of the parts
5VA1 BOOT GND J1W JBUZ JDAC1-JDAC6 JLEDD JP0 JP9 JRC5R JRLY JSPK = AL-AWAIL_V1.0:JP1E: JUMPER
+5V QR1 RS1 SPK = AL-AWAIL_V1.0:AK500/2: CONNECTOR
BAT = AL-AWAIL_V1.0:BATT
C1-C4 C6-C10 C12 C14-C16 C19 C20 C23-C30 C33-C35 C37 C38 C40 = AL-AWAIL_V1.0:CAP: Ceramic Capacitor
C5 C11 C13 C17 C18 C21 C22 C31 C32 C36 C39 = AL-AWAIL_V1.0:ELC: POLARIZED Capacitor
D1-D4 = AL-AWAIL_V1.0:1N4148: DIODE
DSP1 = AL-AWAIL_V1.0:F512SRWBT14: LED DISPLAY 1-character 7 segment, decimal point right, F512SRWBT14
FB1 = AL-AWAIL_V1.0:FB: SMD BEAD INDUCTOR
GLCD = AL-AWAIL_V1.0:LCD128X64: HDM64GS12 128 X 64 Dots Graphic Source: http://www.hantronix.com/down/64gs12-r.pdf
IC1 = AL-AWAIL_V1.0:FT232R: Source: http://www.ftdichip.com/Documents/DataSheets/DS_FT232R_v104.pdf
IC2 = WALID2008A:ATMEGA324P: ATmega164PA/324PA/644PA/1284P
IC3 = AL-AWAIL_V1.0:IR-RECEIVER: IR Receiver
IC4 = AL-AWAIL_V1.0:DS1820: 1?WireTM Digital Thermometer
IC5 = AL-AWAIL_V1.0:LM35: Temperature Sensor
IC6 = WALID2008A:DS1307
IC7 = WALID2008A:AT24C*: 2-wire serial EEPROM
IC8 = WALID2008A:MAX485: RS485 TRANSEIVER
IC9 = WALID2008A:74HC595: 8 BIT SHIFT REGISTER WITH OUTPUT LATCHES (3 STATE)
ISP = WALID2008A:PINHD-1X6: PIN HEADER
J1 = AL-AWAIL_V1.0:DCJ0202: DC POWER JACK Source: DCJ0202.pdf
JAN1 JAN2 JP1 JP2 JP7 = AL-AWAIL_V1.0:JP2E: JUMPER
JP3-JP6 = AL-AWAIL_V1.0:PINHD-1X8: PIN HEADER
JP8 = AL-AWAIL_V1.0:PINHD-1X3: PIN HEADER
JPS = AL-AWAIL_V1.0:JP2Q: JUMPER
K1 = AL-AWAIL_V1.0:G5Q-1: RELAY 1 x switch, Eichhoff/distributor Schukat
LCD = AL-AWAIL_V1.0:LCD16X2: DISPLAY DMC 162C BACKLIGHT 16X2
LDR = photo-elements:?1060*: Sensor Street Light control
LED1 LED2 LED11 LED12 LED14 = WALID2008A:LED: LED 3mm, 5mm
LED3-LED10 = AL-AWAIL_V1.0:LED: LED 3mm, 5mm
NTC = AL-AWAIL_V1.0:NTC: PHILIPS NTC
PS1 = AL-AWAIL_V1.0:PS2-CON: YAMAICHI CONNECTOR
PW1 = AL-AWAIL_V1.0:SW-ON-OFF: SLIDING SWITCH Distributor Buerklin, 11G810
Q1 Q2 Q5 = AL-AWAIL_V1.0:CRYSTAL: Crystals and Crystal Resonators
Q3 Q4 Q6-Q9 = AL-AWAIL_V1.0:BC337: NPN Transistor
R1-R10 R12-R16 R18 R19 R23 R24 R26-R51 R53 = AL-AWAIL_V1.0:RESISTOR: RESISTOR, European symbol
R11 R17 R25 R52 = AL-AWAIL_V1.0:POT: Spain Pot Resistor
RN1 = AL-AWAIL_V1.0:G08R: SIL RESISTOR; OC_FARNELL: unknown; OC_NEWARK: unknown
S1-S20 = AL-AWAIL_V1.0:TAC_SW_M: OMRON SWITCH
S7SEG1 = AL-AWAIL_V1.0:DIP08YL: DIL/CODE SWITCH; OC_FARNELL: unknown; OC_NEWARK: unknown
S21 = AL-AWAIL_V1.0:DIP04YL: DIL/CODE SWITCH; OC_FARNELL: unknown; OC_NEWARK: unknown
S22 = AL-AWAIL_V1.0:DIP06YL: DIL/CODE SWITCH
SG1 = AL-AWAIL_V1.0:BUZZER: BUZZER
X1 = WALID2008A:USB-M-C: BERG USB connector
